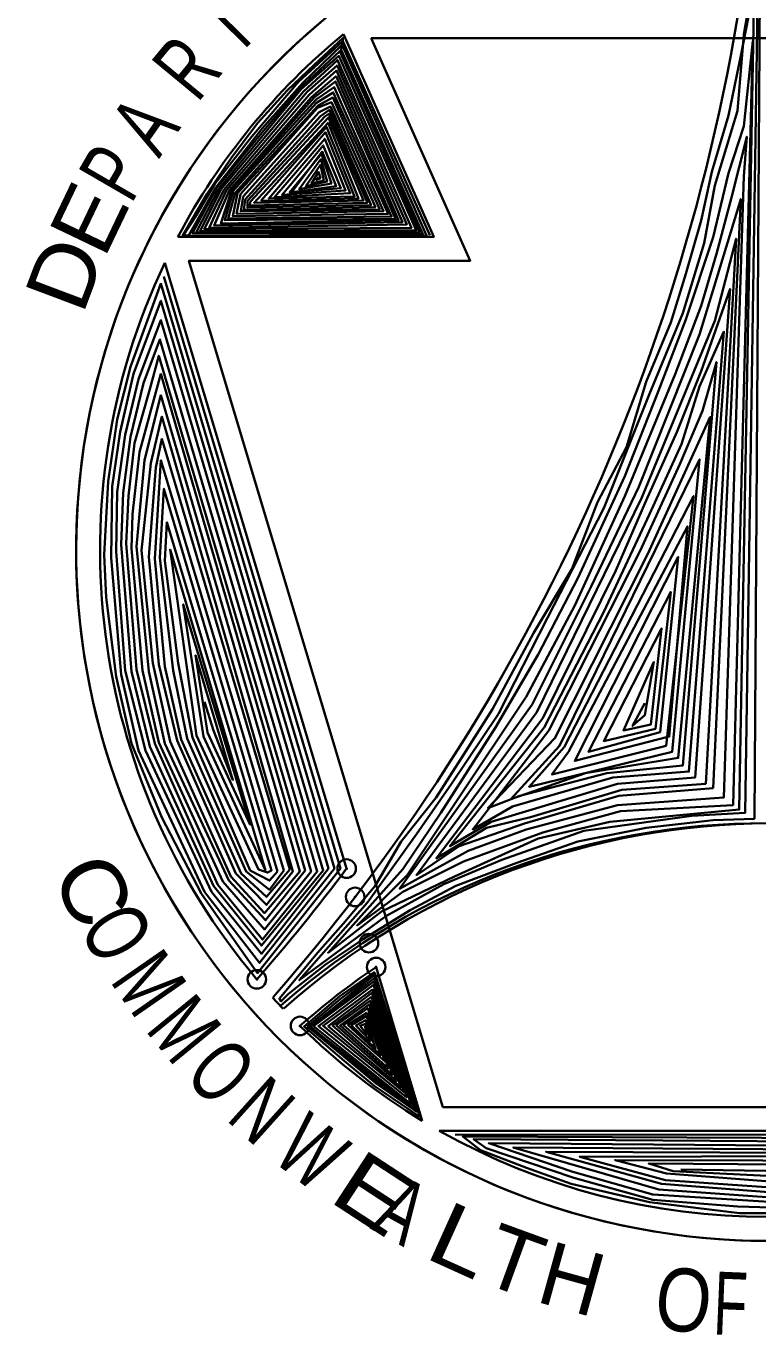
# Model space of a CAD drawing. Extents: x 763.8 to 797.8, y -170.3 to -127.3.
# Drawn here: x 779.224 to 780.741, y -131.504 to -128.791 of the extents above; entities that cross this region are included whole.
import ezdxf
from ezdxf.enums import TextEntityAlignment as Align

# ---------------------------------------------------------------- set-up
doc = ezdxf.new("R2010")
doc.units = 0
doc.header["$LTSCALE"] = 0.077
doc.header["$PDMODE"] = 32
doc.header["$PDSIZE"] = 0.0385
doc.layers.add('1', color=7, linetype='Continuous', lineweight=35)

msp = doc.modelspace()

# ---------------------------------------------------------------- linework, layer by layer
at = {"layer": '1'}
for p, q in [((780.75875, -128.81508), (779.93925, -128.81508)), ((779.51125, -129.28092), (779.88817, -130.53733)), ((779.94933, -130.74142), (780.045, -131.06025)), ((780.08033, -131.08092), (781.44117, -131.08092))]:
    msp.add_line(p, q, dxfattribs=at)
for points in [[(780.74633, -128.50825), (780.73367, -130.434), (780.64842, -130.43717), (780.5095, -130.45292), (780.3675, -130.48142), (780.24117, -130.52558), (780.11492, -130.57292), (780.02017, -130.62342), (779.92233, -130.68342), (779.84342, -130.73708), (779.76767, -130.79708), (779.75183, -130.81283), (779.74867, -130.80658), (779.82758, -130.71183), (779.88125, -130.65183), (779.94758, -130.57292), (780.00125, -130.48142), (780.07383, -130.38983), (780.13067, -130.30142), (780.19067, -130.20667), (780.27592, -130.04883), (780.35483, -129.91625), (780.4085, -129.77733), (780.4685, -129.66367), (780.5095, -129.52792), (780.56008, -129.40483), (780.59158, -129.30383), (780.62317, -129.19333), (780.64525, -129.09225), (780.68, -128.97542), (780.70525, -128.85233), (780.72108, -128.77025)], [(780.74, -128.75133), (780.71475, -130.42142), (780.60425, -130.42775), (780.38008, -130.45925), (780.20967, -130.51925), (780.08967, -130.56975), (779.96967, -130.63608), (779.78975, -130.76867), (779.93175, -130.60767), (780.03283, -130.46558), (780.10542, -130.36142), (780.20333, -130.21617), (780.30433, -130.01733), (780.42117, -129.79), (780.51583, -129.55317), (780.58533, -129.38592), (780.6295, -129.24067), (780.65158, -129.12067), (780.69892, -128.966), (780.71158, -128.80808), (780.73367, -128.67867), (780.70217, -130.41508), (780.43375, -130.44033), (780.28542, -130.47508), (780.11175, -130.554), (779.96025, -130.62658), (779.84975, -130.71183), (780.00442, -130.53817), (780.08333, -130.42142), (780.197, -130.24458), (780.28542, -130.09308), (780.3675, -129.93517), (780.46533, -129.72367), (780.53475, -129.54692), (780.59158, -129.3985), (780.64842, -129.228), (780.68, -129.09542), (780.71158, -128.99758), (780.7305, -128.82075), (780.6895, -130.40558), (780.45583, -130.41825), (780.29483, -130.46242), (780.13067, -130.52242), (780.00442, -130.58558), (779.90967, -130.655), (780.01383, -130.55083), (780.11492, -130.39933), (780.26017, -130.18142), (780.36117, -129.992), (780.46533, -129.76475), (780.5695, -129.51217), (780.62317, -129.37008), (780.65475, -129.26275), (780.68633, -129.14592), (780.71792, -129.01967), (780.71158, -129.10175), (780.67058, -130.38983), (780.44958, -130.40558), (780.26017, -130.45608), (780.14017, -130.50033), (779.99808, -130.57925), (780.27275, -130.19725), (780.39592, -129.951), (780.49375, -129.74575), (780.62008, -129.43008), (780.70525, -129.14908), (780.64842, -130.37083)], [(779.88183, -128.80683), (780.06883, -129.22758), (779.53808, -129.22758)], [(780.06092, -129.22358), (779.88008, -128.82158), (779.78867, -128.90617), (779.69142, -129.01917), (779.61475, -129.11742), (779.57642, -129.18325), (779.54883, -129.2255), (780.054, -129.22458), (779.87908, -128.8295), (779.7975, -128.90808), (779.713, -129.00242), (779.61667, -129.12533), (779.56067, -129.22358), (779.54883, -129.22458), (779.598, -129.13908), (779.65008, -129.06242), (779.70417, -128.99067), (779.76508, -128.92383), (779.82108, -128.87075), (779.88108, -128.81475), (779.87708, -128.83933), (780.04617, -129.22158), (779.5685, -129.21967), (779.61767, -129.12725), (779.71592, -129.00733), (779.78967, -128.92092), (779.87417, -128.84225), (780.03925, -129.21767), (779.57642, -129.21867), (779.62258, -129.12825), (779.79358, -128.92092), (779.87217, -128.85208), (780.03242, -129.21375), (779.58425, -129.21575), (779.6275, -129.12925), (779.7985, -128.92583), (779.86925, -128.86092), (780.02258, -129.20883), (779.59308, -129.21175), (779.63433, -129.12925), (779.80633, -128.92675), (779.86825, -128.87175), (780.01275, -129.20192), (779.60292, -129.20883), (779.63925, -129.13025), (779.81025, -128.93267), (779.86725, -128.8825), (780.00392, -129.197), (779.61375, -129.20392), (779.64517, -129.13025), (779.81517, -128.93758), (779.86633, -128.89433), (779.996, -129.19308), (779.6275, -129.2), (779.64917, -129.13217), (779.82108, -128.93858), (779.86533, -128.90517), (779.98917, -129.19017), (779.63533, -129.19308), (779.65308, -129.13217), (779.825, -128.9425), (779.86233, -128.91692), (779.98125, -129.18525), (779.64225, -129.18917), (779.657, -129.13608), (779.826, -128.94942), (779.86042, -128.92775), (779.97442, -129.17933), (779.65208, -129.18425), (779.66192, -129.13708), (779.82892, -128.95525), (779.85942, -128.93858), (779.96458, -129.17442), (779.65992, -129.17933), (779.66775, -129.13908), (779.828, -128.96017), (779.8565, -128.94842), (779.95675, -129.1705), (779.66875, -129.17442), (779.67367, -129.144), (779.83092, -128.969), (779.8545, -128.95725), (779.94792, -129.16558), (779.67467, -129.1715), (779.67758, -129.14992), (779.83383, -128.97692), (779.8525, -128.96408), (779.939, -129.16167), (779.6825, -129.16658), (779.6825, -129.15283), (779.84275, -128.97783), (779.85158, -128.972), (779.93117, -129.15675), (779.68742, -129.16267), (779.68842, -129.15475), (779.85058, -128.97983), (779.92333, -129.15183), (779.69625, -129.15675), (779.84958, -128.99067), (779.9125, -129.14792), (779.71008, -129.15283)], [(779.93925, -128.81508), (780.1445, -129.27675), (779.56125, -129.27675), (780.08775, -131.03175), (780.96133, -131.03175)], [(781.58217, -128.81508), (781.377, -129.27675), (781.96017, -129.27675), (781.43367, -131.03175), (780.56017, -131.03175)], [(779.71008, -129.15283), (779.84667, -128.9995), (779.90467, -129.144), (779.72675, -129.14792), (779.84467, -129.01033), (779.89575, -129.13708), (779.73858, -129.14492), (779.84275, -129.02408), (779.886, -129.13117), (779.75425, -129.14), (779.83975, -129.03783), (779.87617, -129.12625), (779.77392, -129.13517), (779.83775, -129.05058), (779.86633, -129.12233), (779.77, -129.13517), (779.83583, -129.0555), (779.8565, -129.11642), (779.78967, -129.12825), (779.83483, -129.06633), (779.84767, -129.1125), (779.80342, -129.12233), (779.83383, -129.07808), (779.84075, -129.11058), (779.81517, -129.11642), (779.82992, -129.09283), (779.83383, -129.10567), (779.825, -129.10958), (779.82992, -129.10367)], [(780.64842, -130.37083), (780.45275, -130.38667), (780.257, -130.4435), (780.12125, -130.49083), (780.03283, -130.55083), (780.28225, -130.213), (780.50008, -129.76792), (780.65158, -129.40167), (780.69583, -129.23117), (780.63267, -130.36142), (780.459, -130.374), (780.26958, -130.43083), (780.17808, -130.45292), (780.07383, -130.51608), (780.29483, -130.22567), (780.44642, -129.91942), (780.5095, -129.77417), (780.57267, -129.63217), (780.62317, -129.50583), (780.68317, -129.33533), (780.61058, -130.34875), (780.44958, -130.36142), (780.1875, -130.44033), (780.10225, -130.49083), (780.298, -130.24458), (780.42117, -130.00467), (780.51583, -129.80258), (780.58217, -129.65742), (780.62008, -129.53742), (780.67058, -129.42375), (780.59792, -130.33617), (780.44008, -130.34875), (780.23175, -130.40875), (780.14967, -130.45608), (780.3075, -130.25092), (780.49692, -129.87842), (780.579, -129.69842), (780.62633, -129.58792), (780.65475, -129.48692), (780.58533, -130.3235), (780.42742, -130.33933), (780.2475, -130.38667), (780.18125, -130.41192), (780.32008, -130.26667), (780.51267, -129.88467), (780.64217, -129.60058), (780.57583, -130.30775), (780.38325, -130.33933), (780.22858, -130.393), (780.32958, -130.2825), (780.62008, -129.68892), (780.56325, -130.29508), (780.26642, -130.36775), (780.33908, -130.28567), (780.60742, -129.76475), (780.55058, -130.2825), (780.31383, -130.34242), (780.3485, -130.29508), (780.59475, -129.82783), (780.55692, -130.2635), (780.36117, -130.314), (780.57583, -129.891), (780.53792, -130.25408), (780.38958, -130.29508), (780.56008, -129.96358), (780.5285, -130.24775), (780.42117, -130.273), (780.54108, -130.03942), (780.519, -130.23825), (780.46217, -130.25092), (780.52533, -130.10883), (780.50633, -130.21933), (780.48108, -130.24142), (780.50633, -130.19408)], [(779.50925, -129.3095), (779.87558, -130.537), (779.703, -130.75383), (779.58717, -130.58958), (779.50508, -130.43167), (779.44192, -130.278), (779.41033, -130.139), (779.38925, -129.97483), (779.38508, -129.88642), (779.3935, -129.73483), (779.41242, -129.60642), (779.43975, -129.49692), (779.503, -129.32425), (779.863, -130.537), (779.70717, -130.73283), (779.5935, -130.58542), (779.45667, -130.29275), (779.42083, -130.13483), (779.39983, -129.89275), (779.40192, -129.74533), (779.41875, -129.63158), (779.44608, -129.51158), (779.503, -129.36), (779.85033, -130.537), (779.71142, -130.71383), (779.60825, -130.58542), (779.47142, -130.29275), (779.42925, -130.12642), (779.41033, -129.88008), (779.41242, -129.75583), (779.42925, -129.63792), (779.45667, -129.52217), (779.503, -129.4), (779.83983, -130.54117), (779.71142, -130.697), (779.61242, -130.57275), (779.47983, -130.28433), (779.44192, -130.1285), (779.42083, -129.86533), (779.42508, -129.75792), (779.43975, -129.64217), (779.46717, -129.53058), (779.50083, -129.44), (779.82717, -130.54333), (779.7135, -130.68442), (779.62083, -130.57067), (779.49033, -130.278), (779.45242, -130.12433), (779.43133, -129.86325), (779.43558, -129.76425), (779.44825, -129.65483), (779.47983, -129.54325), (779.49875, -129.47375), (779.81458, -130.54333), (779.71775, -130.66333), (779.63142, -130.56433), (779.49875, -130.27592), (779.46508, -130.12642), (779.44192, -129.87375), (779.444, -129.80217), (779.45875, -129.67375), (779.503, -129.51158), (779.80192, -130.54117), (779.71983, -130.64433), (779.644, -130.56225), (779.51142, -130.278), (779.47775, -130.1285), (779.45242, -129.86958), (779.46925, -129.69058), (779.503, -129.55583), (779.79142, -130.54333), (779.71775, -130.62958), (779.64825, -130.55383), (779.52192, -130.27383), (779.48617, -130.11167), (779.463, -129.878), (779.48192, -129.69692), (779.50508, -129.60008), (779.77667, -130.54333), (779.72192, -130.61275), (779.65875, -130.5475), (779.53667, -130.27167), (779.49875, -130.11383), (779.47775, -129.89058), (779.49242, -129.70533), (779.50508, -129.64633), (779.77033, -130.53908), (779.72192, -130.59592), (779.66925, -130.5475), (779.54508, -130.26958), (779.51142, -130.118), (779.49033, -129.89483), (779.503, -129.69058), (779.75775, -130.54117), (779.72825, -130.58117), (779.67983, -130.54333), (779.55775, -130.2675), (779.52825, -130.12642), (779.50083, -129.89275), (779.50925, -129.7495), (779.74508, -130.54333)], [(779.74508, -130.54333), (779.72825, -130.56225), (779.68825, -130.54117), (779.56825, -130.26542), (779.53875, -130.11167), (779.51142, -129.899), (779.51558, -129.819), (779.7325, -130.54117), (779.724, -130.54542), (779.70508, -130.53908), (779.57667, -130.26117), (779.52192, -129.87583), (779.71983, -130.54117), (779.59142, -130.26325), (779.54925, -129.98958), (779.68825, -130.44642), (779.59983, -130.25483), (779.57458, -130.09483), (779.65242, -130.35383), (779.61242, -130.25067), (779.5935, -130.19167)], [(779.94683, -130.7515), (779.87383, -130.802), (779.80008, -130.8645), (779.87875, -130.93267), (779.94542, -130.98742), (780.04025, -131.052), (779.94683, -130.75433), (779.8745, -130.80833), (779.80717, -130.8645), (779.87875, -130.92417), (779.94967, -130.98317), (780.03392, -131.04142), (779.94617, -130.76417), (779.81275, -130.86525), (780.02967, -131.03442), (779.94475, -130.75925), (779.81342, -130.8645), (779.93625, -130.96775), (780.029, -131.03725), (779.94475, -130.77117), (779.81975, -130.86383), (780.02125, -131.02533), (779.944, -130.77817), (779.82958, -130.86383), (780.01283, -131.01192), (779.94192, -130.788), (779.83942, -130.86308), (780.00725, -131.00075), (779.9405, -130.795), (779.84992, -130.86383), (780.00083, -130.99017), (779.93983, -130.80342), (779.85908, -130.86242), (779.99175, -130.97758), (779.93842, -130.814), (779.937, -130.81117), (779.86675, -130.86175), (779.98333, -130.96492), (779.93492, -130.81892), (779.8745, -130.86242), (779.97492, -130.95158), (779.93208, -130.82658), (779.8815, -130.86175), (779.96792, -130.9375), (779.93, -130.83642), (779.89067, -130.861), (779.95875, -130.92417), (779.92925, -130.84342), (779.89767, -130.86175), (779.94825, -130.91017), (779.92783, -130.85192), (779.9075, -130.86242), (779.93767, -130.89467), (779.92717, -130.85892), (779.91592, -130.86308), (779.93, -130.88133), (779.9265, -130.86525), (779.92433, -130.86592)], [(780.11308, -131.08942), (781.41525, -131.08767)], [(780.80783, -131.25175), (780.70308, -131.25175), (780.51625, -131.22908), (780.35392, -131.19067), (780.26142, -131.1575), (780.16542, -131.12083), (780.12875, -131.09292), (781.36817, -131.09817)], [(780.813, -131.24133), (780.69958, -131.23783), (780.52325, -131.22383), (780.35917, -131.17842), (780.17767, -131.11733), (780.15142, -131.09817), (781.328, -131.10692)], [(780.80783, -131.23083), (780.52325, -131.21342), (780.35742, -131.16625), (780.18283, -131.10692), (781.29133, -131.11558)], [(780.80783, -131.22208), (780.5355, -131.20292), (780.2335, -131.11558), (781.26867, -131.12258)], [(780.80783, -131.21167), (780.54075, -131.19067), (780.30158, -131.12433), (781.20233, -131.12783)], [(780.80783, -131.20117), (780.5495, -131.18367), (780.37142, -131.13483), (781.129, -131.13308)], [(780.80258, -131.18892), (780.55125, -131.16975), (780.44475, -131.14183), (781.05742, -131.14358)], [(780.80083, -131.17675), (780.56517, -131.1645), (780.51458, -131.14883), (780.97542, -131.15225)], [(780.80083, -131.1645), (780.58083, -131.161)]]:
    msp.add_lwpolyline(points, dxfattribs=at)
for centre, radius, start, end in [((780.76073, -129.87583), 1.43338, 0, 351.33483), ((780.76073, -129.87583), 1.43338, 45, 36.33483), ((776.63402, -128.08937), 4.1216, 318.80967, 354.36889), ((780.76073, -129.87583), 1.38388, 129.4259, 152.06902), ((780.76073, -129.87583), 1.38388, 154.54085, 220.08687), ((780.75419, -131.9625), 1.51919, 48.36043, 131.28276), ((780.76727, -131.9625), 1.51919, 48.71724, 131.63957), ((776.63402, -128.08937), 4.0721, 318.88657, 323.04726), ((780.76727, -131.9625), 1.46969, 123.81454, 131.63957), ((780.76073, -129.87583), 1.38388, 222.14966, 223.48887), ((780.76073, -129.87583), 1.38388, 225.53611, 238.85744), ((780.76073, -129.87583), 1.38388, 240.55017, 299.44982)]:
    msp.add_arc(centre, radius, start, end, dxfattribs=at)
for p in [(779.88817, -130.53733), (779.90575, -130.596), (779.9345, -130.69192), (779.94933, -130.74142), (779.702, -130.767), (779.79142, -130.8635)]:
    msp.add_point(p, dxfattribs=at)

# ---------------------------------------------------------------- texts
for s, rotation, width, p in [('T', 45.435, 0.7, (779.6857, -128.82998)), ('R', 50.404, 0.7, (779.6069, -128.91716)), ('A', 54.921, 0.7, (779.52246, -129.03304)), ('P', 59.889, 0.7, (779.46185, -129.12569)), ('E', 64.422, 1.1, (779.41281, -129.21738)), ('D', 69.378, 1.1, (779.36491, -129.32664)), ('C', 296.113, 1.1, (779.30456, -130.61107)), ('O', 300.414, 0.7, (779.35558, -130.70323)), ('M', 304.743, 0.7, (779.42492, -130.81199)), ('M', 309.235, 0.7, (779.50111, -130.91144)), ('O', 313.519, 0.7, (779.58132, -131.00251)), ('N', 318.061, 0.7, (779.66913, -131.0873)), ('W', 322.344, 0.7, (779.77621, -131.17617)), ('E', 326.851, 1.3, (779.91035, -131.26533)), ('A', 331.159, 0.7, (779.97125, -131.30288)), ('L', 335.683, 1.25, (780.10084, -131.36725)), ('T', 339.981, 1.05, (780.213, -131.41189)), ('O', 353.343, 0.85, (780.57955, -131.49679)), ('F', 357.628, 0.65, (780.68146, -131.50466))]:
    msp.add_text(s, height=0.1307, rotation=rotation, dxfattribs=dict(at, width=width)).set_placement(p, align=Align.CENTER)
msp.add_text('H', height=0.1307, rotation=344.488, dxfattribs=at).set_placement((780.33814, -131.45119), align=Align.CENTER)

doc.saveas('drawing.dxf')
